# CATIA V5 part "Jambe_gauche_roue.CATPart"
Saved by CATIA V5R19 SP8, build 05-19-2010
Part number: Jambe_gauche_roue
Bounding box of the stored display mesh (mm): x -975 to -615, y -524.989 to 900, z -644.15 to 166.768
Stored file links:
  G:\EU_thinkMotion\CFAO_2010\MMS_groupe2\MMS_groupe2\OK\mmartini\mmartiniCFAO\Jambe_gauche_roue.CATPart
  C:\Users\Mathieu Martini\Desktop\CFAO\Animation\CFAO.CATProduct
  G:\EU_thinkMotion\CFAO_2010\MMS_groupe2\MMS_groupe2\OK\mmartini\mmartiniCFAO\Squelette.CATPart
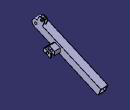
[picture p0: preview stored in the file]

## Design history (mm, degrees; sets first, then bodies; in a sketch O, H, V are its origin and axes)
External parameters (linked from other documents)
  External.diametre_verin = 120 mm
  External.diametre_canon = 150 mm
AxisSystem1: origin (0, 0, 0), X (1, 0, 0), Y (0, 1, 0), Z (0, 0, 1)
Set1
  Sketch1 on Plane1, origin (-825, 0, 0), H (0, 1, 0), V (0, 0, 1)
    circle A1 centre (-450, 0) radius 24
    point P1 (-450, 0)
    reference projected point E1 (-450, 0) from Line1
    line L1 (900, -506.646) -> (-420.0311, 68.7522)
    point P2 (900, -506.646)
    axis line L2 (-450, 0) -> (1598.6842, -893.0162)
    reference projected point E2 (1500, -850) from Line2
    reference intersected line E3 through (900, 0) direction (0, 1) from Plane2
    line L3 (-479.9689, -68.7522) -> (840.0622, -644.1504)
    line L4 (900, -506.646) -> (840.0622, -644.1504)
    point P5 (900, -506.646)
    arc A2 centre (-450, 0) radius 75 from (-420.0311, 68.7522) to (-479.9689, -68.7522) ccw
    radius A1 = 24 {= External.diametre_verin /5}
    distance L1 L2 = 75 {= External.diametre_canon /2}
    distance L3 L2 = 75 {= External.diametre_canon /2}
    coincidence: P1 E1, L2 E2, P2 E3, P2 P5
    perpendicularity: L4 L3
    tangency: A2 L1
Set2
  Plane1 "Plan_jambe_gauche_roue": linked copy from another document
  Line1 "axe_berceau_jambe_roue": linked copy from another document
  Line2 "axe_roue": linked copy from another document
  Plane2 "Plan_berceaumax": linked copy from another document
  Point1 "Point_verin_gauche": linked copy from another document
  Plane3: linked copy from another document
  Line3 "Droite_plan_de_construction_verin": linked copy from another document
  Plane4: linked copy from another document
  Plane5 "Plan_rayon_ext_verin_gauche": linked copy from another document
  Plane6 "Plan_rayon_int_verin_gauche": linked copy from another document
  Point2: linked copy from another document
  Line4: linked copy from another document
Body1 (main body)
  Pad1: profile Sketch1, direction (-1, 0, 0), length 150 {= External.diametre_canon}
  Sketch2 on Plane3, origin (0, 0, 0), H (-1, 0, 0), V (0, 0, 1)
    line L1 (615, -160) -> (825, -160)
    line L2 (825, -160) -> (825, -240)
    line L3 (825, -240) -> (615, -240)
    line L4 (615, -240) -> (615, -160)
    reference intersected line E1 through (825, 0) direction (0, -1) from Plane1
    reference projected line E2 through (0, -200) direction (-1, 0) from Line3
    reference projected line E3 through (0, -200) direction (-1, 0) from Line3
    distance E2 L1 = 40 {= External.diametre_verin /3}
    distance E3 L3 = 40 {= External.diametre_verin /3}
    length L3 = 210 {= External.diametre_canon *1.4}
    horizontal: L1 H, L3 H
    vertical: L2 V, L4 V
    coincidence: L2 E1
  Sketch3 on start face of Pad1, origin (-825, 0, 0), H (0, 1, 0), V (0, 0, 1)
    projected line E1 (900, -506.646) -> (-420.0311, 68.7522) from edge [face of Pad1 from Sketch1.L1 | start face of Pad1]
    projected line E2 (60, -140.4921) -> (-75, -81.646) from edge [face of Pad1 from Sketch1.L1 | start face of Pad1]
    projected line E3 (-479.9689, -68.7522) -> (840.0622, -644.1504) from edge [face of Pad1 from Sketch1.L3 | start face of Pad1]
    projected line E4 (-75, -245.2771) -> (60, -304.1233) from edge [face of Pad1 from Sketch1.L3 | start face of Pad1]
    line L1 (-75, -81.646) -> (-75, -245.2771)
    point P5 (-75, -81.646)
    point P6 (-75, -245.2771)
    line L2 (60, -140.4921) -> (60, -304.1233)
    point P7 (60, -140.4921)
    point P8 (60, -304.1233)
    reference projected point E5 (0, -200) from Point1
    reference projected point E6 (0, -200) from Point1
    distance L2 E5 = 60 {= External.diametre_verin /2}
    distance L1 E6 = 75 {= External.diametre_canon /2}
    coincidence: P5 E1, P6 E3, P7 E1, P8 E3
    vertical: L1 V, L2 V
  SolidCombine1: FirstComponentProfile Sketch2, FirstComponentDirection Sketch3.E4, SecondComponentProfile Sketch3, SecondComponentDirection Sketch3
  Chamfer1: length 30 {= External.diametre_canon /10*2}, angle 45, on edge [face of SolidCombine1 from Sketch2.L1 | face of SolidCombine1 from Sketch3.L1]
  Sketch4 on face of SolidCombine1 from Sketch2.L4, origin (-615, 0, 0), H (0, 1, 0), V (0, 0, 1)
    circle A1 centre (0, -200) radius 24
    point P1 (0, -200)
    reference projected point E1 (0, -200) from Point1
    radius A1 = 24 {= External.diametre_verin /5}
    coincidence: P1 E1
  Pocket1: profile Sketch4, direction (-1, 0, 0), up to start face of Pad1
  Sketch5 on face of Pad1 from Sketch1.L4, origin (0, 941.8819, -410.5639), H (-1, 0, 0), V (0, 0.3996, 0.9167)
    line L1 (840, -119.8134) -> (960, -119.8134)
    line L2 (960, -119.8134) -> (960, -239.8134)
    line L3 (960, -239.8134) -> (840, -239.8134)
    line L4 (840, -239.8134) -> (840, -119.8134)
    reference projected line E2 (825, -104.8134) -> (975, -104.8134) from edge [face of Pad1 from Sketch1.L4 | face of Pad1 from Sketch1.L1]
    reference projected line E3 (975, -254.8134) -> (975, -104.8134) from edge [end face of Pad1 | face of Pad1 from Sketch1.L4]
    length L2 = 120 {= External.diametre_verin}
    length L1 = 120 {= External.diametre_verin}
    distance L1 E2 = 15 {= (External.diametre_canon -External.diametre_verin )/2}
    distance L2 E3 = 15 {= (External.diametre_canon -External.diametre_verin )/2}
    horizontal: L1 H, L3 H
    vertical: L2 V, L4 V
  Pocket2: profile Sketch5, direction (0, -0.9167, 0.3996), up to Plane3
  Sketch6 on Plane4, origin (0, 0, 0), H (1, 0, 0), V (0, 1, 0)
    line L1 (-645, -57.1429) -> (-705, -57.1429)
    line L2 (-705, -57.1429) -> (-705, 75)
    line L3 (-705, 75) -> (-645, 75)
    line L4 (-645, 75) -> (-645, -57.1429)
    reference intersected line E1 through (-615, 0) direction (0, 1) from Plane6
    reference projected line E2 through (0, 0) direction (1, 0) from Line3
    reference intersected line E3 through (-735, 0) direction (0, 1) from Plane5
    reference projected line E4 through (0, 0) direction (1, 0) from Line3
    distance L4 E1 = 30 {= External.diametre_canon /5}
    distance L3 E2 = 75 {= External.diametre_canon /2}
    distance L2 E3 = 30 {= External.diametre_canon /5}
    distance E4 L1 = 57.1429 {= External.diametre_verin/2.1}
    horizontal: L1 H, L3 H
    vertical: L2 V, L4 V
  Pocket3: profile Sketch6, direction (0, 0, -1), up to face of SolidCombine1 from Sketch2.L3
  Sketch7 on face of Pad1 from Sketch1.L1, origin (0, -41.8819, -96.0821), H (-1, 0, 0), V (0, -0.9167, 0.3996)
    line L1 (825, 412.5132) -> (900, 412.5132)
    line L2 (900, 412.5132) -> (900, 292.5132)
    line L3 (900, 292.5132) -> (825, 292.5132)
    line L4 (825, 292.5132) -> (825, 412.5132)
    reference projected line E1 (825, 412.5132) -> (975, 412.5132) from edge [face of Pad1 from Sketch1.L1 | face of Pad1 from Sketch1.A2]
    reference projected line E2 (825, -1027.4747) -> (825, 412.5132) from edge [face of Pad1 from Sketch1.L1 | start face of Pad1]
    distance L4 L2 = 75 {= External.diametre_canon /2}
    distance L3 L1 = 120 {= External.diametre_verin}
    horizontal: L1 H, L3 H
    vertical: L2 V, L4 V
    coincidence: E1 L1, L4 E2
  Pad2: profile Sketch7, direction (0, 0.3996, 0.9167), length 120 {= External.diametre_verin}
  Sketch8 on end face of Pad2, origin (0, 6.0683, 13.9215), H (-1, 0, 0), V (0, -0.9167, 0.3996)
    line L1 (840, 412.5132) -> (885, 412.5132)
    line L2 (885, 412.5132) -> (885, 292.5132)
    line L3 (885, 292.5132) -> (840, 292.5132)
    line L4 (840, 292.5132) -> (840, 412.5132)
    reference projected line E1 (900, 292.5132) -> (900, 412.5132) from edge [face of Pad2 from Sketch7.L2 | end face of Pad2]
    reference projected line E2 (825, 412.5132) -> (825, 292.5132) from edge [face of Pad2 from Sketch7.L4 | end face of Pad2]
    reference projected line E3 (900, 412.5132) -> (825, 412.5132) from edge [face of Pad2 from Sketch7.L1 | end face of Pad2]
    reference projected line E4 (825, 292.5132) -> (900, 292.5132) from edge [face of Pad2 from Sketch7.L3 | end face of Pad2]
    distance E1 L2 = 15 {= External.diametre_canon /10}
    distance L4 E2 = 15 {= External.diametre_canon /10}
    horizontal: L1 H, L3 H
    vertical: L2 V, L4 V
    coincidence: L1 E3, L3 E4
  Pocket4: profile Sketch8, direction (0, -0.3996, -0.9167), up to face of Pad1 from Sketch1.L1
  Sketch9 on Plane1, origin (-825, 0, 0), H (0, 1, 0), V (0, 0, 1)
    axis line L1 (-275.5543, 85.8394) -> (-379.3317, 131.9627)
    reference projected point E1 (-376.0481, 130.5033) from Point2
    reference projected line E2 through (-74.2268, -167.0103) direction (0.9138, -0.4061) from Line4
    circle A1 centre (-330.3575, 110.1964) radius 24
    point P3 (-330.3575, 110.1964)
    reference projected point E3 (-376.0481, 130.5033) from Point2
    distance E3 P3 = 50 {= External.diametre_canon /3}
    radius A1 = 24 {= External.diametre_verin /5}
    coincidence: L1 E1, P3 L1
    parallelism: L1 E2
  Pocket5: profile Sketch9, direction (-1, 0, 0), through (limit type 3)
  Chamfer2: length 30 {= External.diametre_canon /5}, angle 45, on edge [face of Pad2 from Sketch7.L1 | end face of Pad2] (x2); edge [face of Pad2 from Sketch7.L3 | end face of Pad2] (x2)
